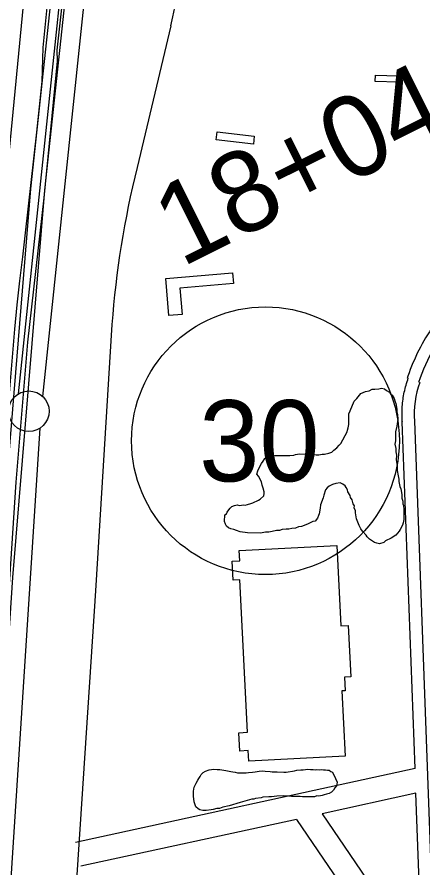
# Model space of a CAD drawing. Extents: x 3313447 to 3351316, y 703786 to 729172.
# Drawn here: x 3325935 to 3326436, y 711398 to 712446 of the extents above; entities that cross this region are included whole.
import ezdxf

# ---------------------------------------------------------------- set-up
doc = ezdxf.new("R2010")
doc.units = 0
for name, color, linetype in [('V-BLDG-OTLN', 7, 'Continuous'), ('V-RAIL-TRAK', 7, 'Continuous'), ('V-ROAD-CNTR', 7, 'Continuous'), ('V-ROAD-IDEN', 7, 'Continuous'), ('V-SITE-VEGE', 7, 'Continuous'), ('V-SURV-IDEN', 7, 'Continuous'), ('V-SURV-LINE', 7, 'Continuous'), ('V-UTIL-LINE', 7, 'Continuous')]:
    doc.layers.add(name, color=color, linetype=linetype)

msp = doc.modelspace()

# ---------------------------------------------------------------- linework, layer by layer
at = {"layer": 'V-BLDG-OTLN'}
for points in [[(3326377, 712374.3), (3326405.3, 712373.5), (3326405.1, 712365.8), (3326376.8, 712366.6)], [(3326181.9, 712304.6), (3326227.8, 712299.3), (3326226.7, 712289.4), (3326180.8, 712294.7)], [(3326122.6, 712078), (3326118.8, 712123.5), (3326201.1, 712130.5), (3326202.2, 712117.3), (3326136.1, 712111.7), (3326138.9, 712079.3)], [(3326339.7, 711534.6), (3326221, 711528.6), (3326220.4, 711541.5), (3326210, 711541), (3326208.9, 711563.6), (3326219.4, 711564.1), (3326209.9, 711752.2), (3326201.7, 711751.8), (3326200.5, 711775.3), (3326209.8, 711775.7), (3326209.2, 711788.4), (3326329.6, 711794.4), (3326334.6, 711695.4), (3326343.6, 711695.9), (3326346.8, 711632.7), (3326338.9, 711632.3), (3326339.7, 711615.3), (3326335.6, 711615.1)]]:
    msp.add_lwpolyline(points, close=True, dxfattribs=at)
at = {"layer": 'V-RAIL-TRAK'}
for points in [[(3325967.5, 712408.6), (3325982.3, 712556.7), (3326001.9, 712726.4), (3326018, 712888.9)], [(3326036.1, 712889.3), (3326023.9, 712770.3), (3326005.4, 712593.9), (3325984.5, 712405.3)], [(3325984.5, 712405.3), (3325984.8, 712391.7), (3325968.4, 712223), (3325948.2, 712045.3), (3325934.1, 711872.6), (3325918.1, 711633.5), (3325902.3, 711385.8), (3325887.1, 711134.1), (3325878.4, 710982.9), (3325865.4, 710787.1), (3325863.1, 710744.4)], [(3325946, 712179.9), (3325953, 712242.1), (3325959.7, 712304.3), (3325966.3, 712366.4), (3325967.5, 712408.6)], [(3325850.3, 710809.5), (3325853.8, 710863.2), (3325857.2, 710916.9), (3325860.6, 710970.6), (3325867.3, 711071.6), (3325873.7, 711172.5), (3325879.8, 711273.5), (3325886, 711378.7), (3325898.7, 711565.9), (3325911, 711744.6), (3325921.6, 711912.8), (3325923.4, 711942.6), (3325925.4, 711972.3), (3325927.6, 712002), (3325930.1, 712031.8), (3325932.8, 712061.4), (3325935.7, 712091.1), (3325938.9, 712120.7), (3325942.4, 712150.4), (3325946, 712179.9)]]:
    msp.add_lwpolyline(points, dxfattribs=at)
at = {"layer": 'V-ROAD-CNTR'}
for points in [[(3325856.5, 710862.8), (3325880.5, 711267), (3325913, 711756.4), (3325952.3, 712234.2), (3326053.8, 713180.2), (3326145.7, 714045.9)], [(3326162.7, 714044.1), (3326070.7, 713178.4), (3325969.3, 712232.6), (3325929.9, 711755.1), (3325897.4, 711265.9), (3325873.5, 710861.8)], [(3326124.8, 712435), (3326083.3, 712260.4)], [(3326464.4, 712085.8), (3326461.6, 712082.5), (3326458.9, 712079.1), (3326456.2, 712075.7), (3326453.6, 712072.3), (3326451, 712068.7), (3326448.5, 712065.2), (3326446, 712061.6), (3326443.6, 712057.9), (3326441.3, 712054.3), (3326439, 712050.5), (3326436.9, 712046.8), (3326434.7, 712043), (3326432.6, 712039.2), (3326430.6, 712035.3), (3326428.7, 712031.4), (3326426.9, 712027.5), (3326425.1, 712023.5), (3326423.3, 712019.5), (3326421.7, 712015.5), (3326420.1, 712011.4), (3326418.6, 712007.3), (3326417.2, 712003.2), (3326416.2, 712000.3)], [(3326052.4, 712067), (3326032.1, 711738.7), (3326005.3, 711331.9)], [(3326410.3, 711946.4), (3326410.2, 711947.9), (3326410, 711950.1), (3326409.9, 711952.3), (3326409.9, 711954.6), (3326409.9, 711956.8), (3326409.9, 711959), (3326409.9, 711961.3), (3326410, 711963.5), (3326410.2, 711965.8), (3326410.4, 711968), (3326410.6, 711970.2), (3326410.8, 711972.4), (3326411.1, 711974.7), (3326411.5, 711976.9), (3326411.8, 711979.1), (3326412.2, 711981.3), (3326412.7, 711983.5), (3326413.2, 711985.7), (3326413.7, 711987.9), (3326414.2, 711990), (3326414.9, 711992.2), (3326415.5, 711994.4), (3326416.2, 711996.5), (3326416.9, 711998.6), (3326417.6, 712000.7)], [(3326426, 711519.3), (3326410.2, 711947.1)], [(3326425.2, 711947.6), (3326476, 710569.1), (3326516, 709785.5), (3326536.8, 709183.7)], [(3326426, 711519.3), (3326007.5, 711428.3)], [(3326427.1, 711488.9), (3326311.5, 711463.7)], [(3326434.7, 711282.5), (3326427.1, 711488.9)], [(3326311.5, 711463.7), (3326434.7, 711282.5)], [(3326279.9, 711456.8), (3326013.9, 711399)], [(3326279.9, 711456.8), (3326436.8, 711226.1)]]:
    msp.add_lwpolyline(points, dxfattribs=at)
for centre, radius, start, end in [((3324912.5, 712714.4), 1244.1, 347.0248, 355.5588), ((3327206.4, 711981.5), 1157.2, 166.0563, 175.7656), ((3326653.2, 711922.8), 234.4, 139.1933, 161.9159), ((3326538.3, 711956.8), 113.4, 159.9752, 184.6331)]:
    msp.add_arc(centre, radius, start, end, dxfattribs=at)
at = {"layer": 'V-ROAD-IDEN'}
msp.add_circle((3326241.6, 711923.6), 165, dxfattribs=at)
msp.add_circle((3326241.6, 711923.6), 165, dxfattribs=at)
at = {"layer": 'V-SITE-VEGE'}
for points in [[(3326344.3, 711943.6), (3326344.5, 711956.6), (3326345.9, 711960.7), (3326350.9, 711972.3), (3326354.4, 711975.7), (3326359.2, 711981.8), (3326364.8, 711984.5), (3326369.6, 711985.1), (3326373.1, 711987.1), (3326376.5, 711987.1), (3326381.3, 711987.7), (3326384.8, 711988.3), (3326388.2, 711987.6), (3326390.9, 711985.5), (3326394.3, 711983.4), (3326395.6, 711981.3), (3326397.7, 711979.9), (3326400.4, 711975.8), (3326401, 711973), (3326402.4, 711969.5), (3326403.6, 711962.7), (3326403.6, 711959.2), (3326404.2, 711955.8), (3326404.8, 711950.3), (3326403.3, 711941.4), (3326401.9, 711934.5), (3326401.7, 711923.5), (3326401, 711919.4), (3326402.3, 711913.9), (3326402.2, 711909.8), (3326402.9, 711905.7), (3326402.8, 711900.2), (3326404.1, 711892.6), (3326404, 711887.1), (3326405.3, 711880.2), (3326405.9, 711876.1), (3326405.8, 711873.3), (3326406.5, 711871.3), (3326407.1, 711867.1), (3326408.5, 711864.4), (3326409.8, 711857.5), (3326409.7, 711852.7), (3326411, 711849.2), (3326411, 711845.8), (3326411.6, 711843.7), (3326412.2, 711838.9), (3326412.1, 711826.5), (3326411.3, 711822.4), (3326410.6, 711819.7), (3326407.8, 711814.2), (3326406.4, 711812.2), (3326402.2, 711807.4), (3326396.6, 711803.4), (3326389.7, 711800.1), (3326387.6, 711798), (3326382.1, 711796.7), (3326378.7, 711797.5), (3326376, 711798.2), (3326369.8, 711802.4), (3326367.1, 711805.2), (3326365.8, 711807.2), (3326361, 711812.1), (3326359, 711814.9), (3326357, 711819), (3326353.7, 711827.3), (3326352.4, 711834.9), (3326352.5, 711837), (3326351.1, 711841.1), (3326351.2, 711843.2), (3326349.8, 711845.9), (3326348.5, 711850.8)], [(3326348.5, 711850.8), (3326346.5, 711853.5), (3326345.9, 711856.3), (3326343.2, 711860.5), (3326342.5, 711863.2), (3326341.2, 711866), (3326339.8, 711868.1), (3326337.1, 711870.2), (3326333.7, 711871.6), (3326328.2, 711871), (3326324.1, 711869.6), (3326319.9, 711867.6), (3326317.8, 711865.6), (3326315.7, 711862.9), (3326313.6, 711856.7), (3326312.8, 711853.3), (3326309.3, 711844.4), (3326309.2, 711840.3), (3326307.8, 711833.5), (3326307, 711831.4), (3326305.6, 711828), (3326302.8, 711824.6), (3326300.1, 711823.9), (3326293.2, 711820.6), (3326286.2, 711818), (3326282.1, 711817.3), (3326278.7, 711816), (3326273.9, 711815.4), (3326270.4, 711814.7), (3326267, 711814.8), (3326262.2, 711814.2), (3326258.7, 711812.8), (3326255.3, 711812.9), (3326249.8, 711811.6), (3326245.6, 711811), (3326241.5, 711811), (3326235.3, 711809.7), (3326219.5, 711809.9), (3326210.6, 711811.4), (3326205.8, 711812.9), (3326202.4, 711814.3), (3326199, 711815), (3326196.2, 711816.4), (3326193.5, 711818.5), (3326192.2, 711820.6), (3326190.9, 711824.1), (3326190.9, 711826.8), (3326191.6, 711829.6), (3326191.6, 711832.3), (3326193.7, 711833.6), (3326194.4, 711835.7), (3326196.5, 711838.4), (3326197.9, 711840.5), (3326200, 711842.5), (3326203.5, 711843.8), (3326206.9, 711844.5), (3326209.7, 711843.7), (3326214.5, 711844.4), (3326216.5, 711844.3), (3326219.3, 711845), (3326223.4, 711846.3), (3326226.2, 711846.9), (3326233.1, 711850.3), (3326235.2, 711851.6), (3326239.4, 711855.7), (3326240.1, 711858.4), (3326240.1, 711860.5), (3326238.8, 711865.3), (3326237.5, 711868.8), (3326236.9, 711872.9), (3326232.8, 711879.8), (3326230.8, 711882.6), (3326232.2, 711886.7), (3326233.6, 711889.4), (3326236.5, 711895.6), (3326238.6, 711898.3), (3326240.7, 711901.7), (3326242.8, 711903.7), (3326248.3, 711905), (3326250.3, 711905), (3326253.1, 711905.6), (3326271.6, 711905.4), (3326276.5, 711906), (3326278.5, 711906.7), (3326283.4, 711907.3), (3326293.7, 711907.2), (3326299.1, 711907.1), (3326303.9, 711906.3), (3326307.4, 711906.3), (3326311.5, 711906.9), (3326314.3, 711906.9), (3326319.8, 711908.2), (3326323.2, 711909.5), (3326326, 711912.2), (3326329.5, 711914.9), (3326332.3, 711918.3), (3326334.4, 711920.3), (3326342.1, 711934.7), (3326342.8, 711936.7), (3326343.6, 711939.4), (3326344.3, 711943.6)]]:
    msp.add_lwpolyline(points, dxfattribs=at)
msp.add_lwpolyline([(3326327.7, 711507), (3326330.1, 711502.8), (3326329.7, 711500.1), (3326329, 711498), (3326327.2, 711495.6), (3326325.5, 711492.9), (3326323, 711490.5), (3326319.9, 711488.8), (3326316.8, 711487.8), (3326314, 711487.2), (3326311.6, 711486.2), (3326307.4, 711485.5), (3326305, 711485.6), (3326302.2, 711484.6), (3326291.6, 711484.7), (3326287.1, 711484.4), (3326284.3, 711484.8), (3326273.6, 711485), (3326270.2, 711485.4), (3326264, 711485.8), (3326255.4, 711485.2), (3326249.2, 711484.6), (3326245.7, 711484.7), (3326238.5, 711484.1), (3326236.1, 711483.4), (3326229.5, 711482.5), (3326227.1, 711481.8), (3326224.6, 711481.5), (3326210.5, 711477.6), (3326197, 711473.6), (3326189, 711471.7), (3326184.9, 711470.3), (3326181.8, 711470), (3326177.3, 711469.1), (3326174.8, 711468.4), (3326168.6, 711467.8), (3326164.5, 711467.8), (3326160.7, 711468.6), (3326158.6, 711469.7), (3326155.9, 711472.4), (3326154.6, 711475.9), (3326153.9, 711478.3), (3326153.3, 711482.1), (3326152.7, 711484.9), (3326152.7, 711491.5), (3326153.8, 711496.6), (3326154.9, 711499), (3326156.3, 711501.4), (3326158.1, 711505.2), (3326159.5, 711507.2), (3326160.9, 711509.6), (3326162.3, 711512.3), (3326164.8, 711514.4), (3326167.6, 711516.4), (3326172.1, 711517.7), (3326175.2, 711518.4), (3326177.2, 711518.7), (3326182.1, 711518.3), (3326185.2, 711518.2), (3326187.9, 711517.9), (3326192.7, 711517.1), (3326198.9, 711516), (3326201.3, 711515.3), (3326204.1, 711514.9), (3326207.2, 711514.1), (3326217.9, 711514), (3326220.6, 711514.6), (3326225.8, 711514.9), (3326228.9, 711515.2), (3326233.7, 711516.2), (3326237.5, 711516.5), (3326241.3, 711516.1), (3326247.2, 711516), (3326249.9, 711515.6), (3326256.1, 711515.2), (3326264.1, 711515.1), (3326267.2, 711515), (3326277.2, 711516.6), (3326280.3, 711517.3), (3326285.1, 711517.9), (3326287.9, 711517.9), (3326293.7, 711518.5), (3326297.2, 711518.1), (3326300.3, 711518.4), (3326302.7, 711518), (3326304.8, 711518.3), (3326307.9, 711517.9), (3326311, 711518.2), (3326313, 711517.9), (3326315.5, 711517.8), (3326318.2, 711517.4), (3326320.3, 711517.4), (3326322, 711516), (3326324.4, 711514.9)], close=True, dxfattribs=at)
at = {"layer": 'V-SURV-LINE'}
for points in [[(3325937.1, 711981.4), (3326067, 713218.3)], [(3326096.8, 713215.2), (3325966.9, 711978.2)], [(3325963.6, 711939.1), (3325880.5, 710655.9)]]:
    msp.add_lwpolyline(points, dxfattribs=at)
msp.add_circle((3325949.9, 711960), 25, dxfattribs=at)
at = {"layer": 'V-UTIL-LINE'}
msp.add_lwpolyline([(3325922.7, 712247.8), (3325980.9, 712848.7), (3326062.4, 713563.7), (3326076.4, 713723.2), (3326120.6, 714144.7), (3326139.3, 714433.5), (3326139.3, 714744.4), (3326141.6, 714989)], dxfattribs=at)

# ---------------------------------------------------------------- texts
at = {"layer": 'V-ROAD-IDEN'}
msp.add_text('30', height=100, rotation=0.0833, dxfattribs=at).set_placement((3326159.8, 711873.5))
at = {"layer": 'V-SURV-IDEN'}
msp.add_text('18+04.5', height=100, rotation=26.5332, dxfattribs=at).set_placement((3326138.1, 712137))

doc.saveas('drawing.dxf')
